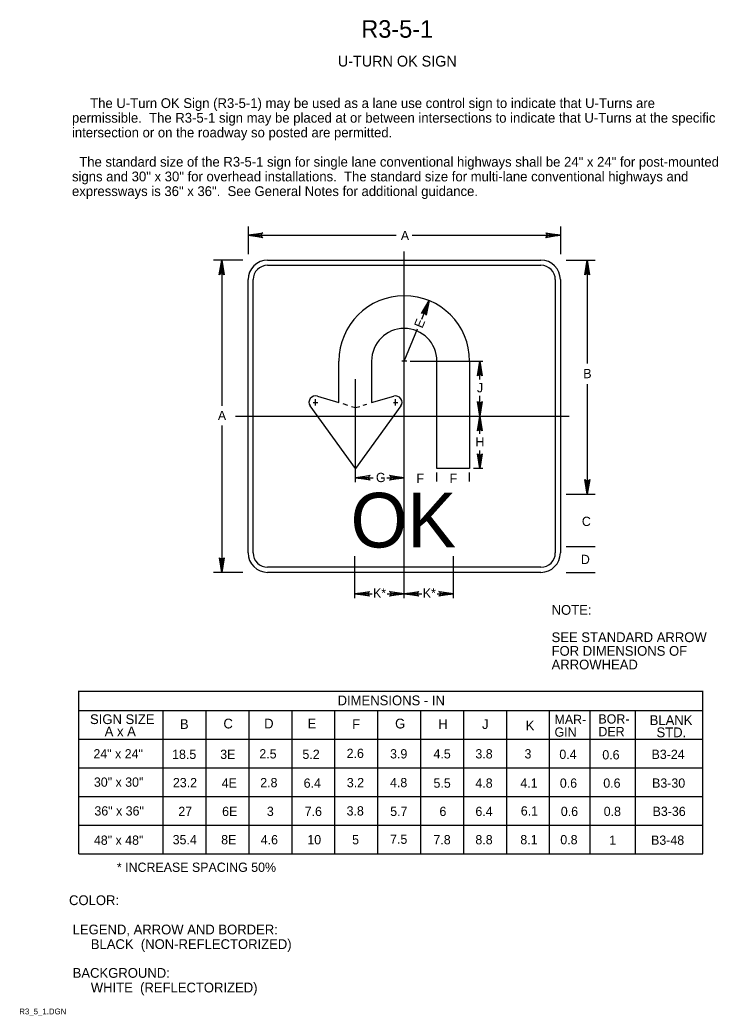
# Model space of a CAD drawing. Extents: x 0.013 to 0.191, y 0.004 to 0.259.
import ezdxf

# ---------------------------------------------------------------- set-up
doc = ezdxf.new("R2010")
doc.units = 0
for name, color, linetype in [('1', 7, 'Continuous'), ('11', 7, 'Continuous'), ('12', 7, 'Continuous'), ('3', 7, 'Continuous')]:
    doc.layers.add(name, color=color, linetype=linetype)

# ---------------------------------------------------------------- blocks, each defined once
blk = doc.blocks.new('RARROW')
at = {"layer": '3'}
for p, q in [((-2.156, 0.28500000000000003), (-2.2665, 0.384625)), ((-2.2665, 0.384625), (0, 0)), ((0, 0), (-2.2665, -0.379125)), ((-2.156, 0.28500000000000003), (-2.075625, 0.12075)), ((0, 0), (-2.156, 0.28500000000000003)), ((-2.14975, -0.2705), (0, 0)), ((-2.075625, 0.12075), (0, 0)), ((0, 0), (-2.074, -0.108)), ((-2.2665, -0.379125), (-2.14975, -0.2705)), ((-2.074, -0.108), (-2.14975, -0.2705))]:
    blk.add_line(p, q, dxfattribs=at)

msp = doc.modelspace()

# ---------------------------------------------------------------- linework, layer by layer
at = {"layer": '1'}
for p, q in [((0.07100000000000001, 0.20626642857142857), (0.07100000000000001, 0.19914142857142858)), ((0.151, 0.20626642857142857), (0.151, 0.19914142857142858)), ((0.07100000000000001, 0.20401642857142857), (0.10893749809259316, 0.20401642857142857)), ((0.11306250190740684, 0.20401642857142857), (0.151, 0.20401642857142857)), ((0.111, 0.11101642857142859), (0.111, 0.19989142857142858)), ((0.069625, 0.19764142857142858), (0.062125, 0.19764142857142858)), ((0.06425, 0.19764142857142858), (0.06425, 0.1602664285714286)), ((0.1525, 0.19764142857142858), (0.15987500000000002, 0.19764142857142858)), ((0.15787500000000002, 0.19764142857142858), (0.15787500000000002, 0.17114142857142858)), ((0.1155, 0.18251642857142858), (0.11737500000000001, 0.18726642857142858)), ((0.111, 0.17176688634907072), (0.11439386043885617, 0.18000911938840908)), ((0.111625, 0.17176642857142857), (0.110375, 0.17176642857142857)), ((0.1125, 0.17176642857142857), (0.131125, 0.17176642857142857)), ((0.130375, 0.1670164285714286), (0.130375, 0.17176642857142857)), ((0.0985, 0.14076642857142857), (0.0985, 0.16714142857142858)), ((0.15787500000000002, 0.16589142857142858), (0.15787500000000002, 0.13764142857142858)), ((0.08762500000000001, 0.16114142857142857), (0.088875, 0.16114142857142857)), ((0.08825, 0.16039142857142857), (0.08825, 0.1620164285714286)), ((0.09525, 0.16089142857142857), (0.0965, 0.1605164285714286)), ((0.10825, 0.16114142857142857), (0.109375, 0.16114142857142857)), ((0.10875, 0.16039142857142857), (0.10875, 0.1620164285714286)), ((0.130375, 0.15764142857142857), (0.130375, 0.16289142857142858)), ((0.0975, 0.16014142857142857), (0.0985, 0.15989142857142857)), ((0.0985, 0.15989142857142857), (0.099625, 0.16014142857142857)), ((0.1005, 0.1605164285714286), (0.101375, 0.1607664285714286)), ((0.06775, 0.15764142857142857), (0.15325, 0.15764142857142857)), ((0.130375, 0.15314142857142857), (0.130375, 0.15764142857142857)), ((0.06425, 0.15526642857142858), (0.06425, 0.11764142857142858)), ((0.130375, 0.14426642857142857), (0.130375, 0.1488914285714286)), ((0.098375, 0.1443914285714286), (0.0985, 0.14426642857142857)), ((0.11937500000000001, 0.14089142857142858), (0.11937500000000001, 0.14326642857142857)), ((0.12775, 0.14089142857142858), (0.12775, 0.14326642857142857)), ((0.131125, 0.14426642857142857), (0.12875, 0.14426642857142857)), ((0.0985, 0.1418918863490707), (0.10300000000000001, 0.1418918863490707)), ((0.1065, 0.14189142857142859), (0.111, 0.14189142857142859)), ((0.1525, 0.13764142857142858), (0.15987500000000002, 0.13764142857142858)), ((0.1525, 0.12426642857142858), (0.15987500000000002, 0.12426642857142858)), ((0.098375, 0.11101642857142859), (0.098375, 0.12176642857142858)), ((0.123625, 0.11101642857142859), (0.123625, 0.12176642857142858)), ((0.069625, 0.11764142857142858), (0.062125, 0.11764142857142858)), ((0.1525, 0.11764142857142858), (0.15987500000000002, 0.11764142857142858)), ((0.098375, 0.11214188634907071), (0.10275000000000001, 0.11214188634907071)), ((0.10664094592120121, 0.11214188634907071), (0.111, 0.11214188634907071)), ((0.111, 0.11214188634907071), (0.1155, 0.11214188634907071)), ((0.11945450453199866, 0.11214188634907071), (0.123625, 0.11214188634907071)), ((0.027625, 0.04551642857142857), (0.027625, 0.08726642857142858)), ((0.027631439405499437, 0.0872120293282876), (0.18750658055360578, 0.0872120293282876)), ((0.18750658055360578, 0.04550602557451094), (0.18750658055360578, 0.08725602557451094)), ((0.027618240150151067, 0.08223667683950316), (0.18750658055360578, 0.08223667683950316)), ((0.049255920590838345, 0.04548667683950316), (0.049255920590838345, 0.08225602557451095)), ((0.06025592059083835, 0.04548667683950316), (0.06025592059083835, 0.08225602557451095)), ((0.07125592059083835, 0.04548667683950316), (0.07125592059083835, 0.08225602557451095)), ((0.08225592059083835, 0.04548667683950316), (0.08225592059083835, 0.08225602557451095)), ((0.09325592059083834, 0.04548667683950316), (0.09325592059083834, 0.08225602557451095)), ((0.10425592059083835, 0.04548667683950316), (0.10425592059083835, 0.08225602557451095)), ((0.11525592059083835, 0.04548667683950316), (0.11525592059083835, 0.08225602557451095)), ((0.12625592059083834, 0.04548667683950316), (0.12625592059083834, 0.08225602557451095)), ((0.13725592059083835, 0.04548667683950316), (0.13725592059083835, 0.08225602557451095)), ((0.14825592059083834, 0.04548667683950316), (0.14825592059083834, 0.08225602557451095)), ((0.14825592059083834, 0.08225602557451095), (0.18750658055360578, 0.08225602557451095)), ((0.15864878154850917, 0.04550602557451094), (0.15864878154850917, 0.08225602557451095)), ((0.17021348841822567, 0.04550602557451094), (0.17021348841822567, 0.08225602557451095)), ((0.17025592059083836, 0.04548667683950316), (0.17025592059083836, 0.08225602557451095)), ((0.027618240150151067, 0.07488667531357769), (0.18750658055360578, 0.07488667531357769)), ((0.14825592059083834, 0.07490602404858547), (0.18750658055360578, 0.07490602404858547)), ((0.027618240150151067, 0.06753667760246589), (0.18750658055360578, 0.06753667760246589)), ((0.14825592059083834, 0.06755602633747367), (0.18750658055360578, 0.06755602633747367)), ((0.027618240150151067, 0.060186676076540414), (0.18750658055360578, 0.060186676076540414)), ((0.14825592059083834, 0.0602060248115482), (0.18750658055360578, 0.0602060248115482)), ((0.027618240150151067, 0.05283667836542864), (0.18750658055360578, 0.05283667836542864)), ((0.14825592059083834, 0.052856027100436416), (0.18750658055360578, 0.052856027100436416)), ((0.027618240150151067, 0.04548667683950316), (0.18750658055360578, 0.04548667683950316)), ((0.14825592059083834, 0.04550602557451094), (0.18750658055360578, 0.04550602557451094))]:
    msp.add_line(p, q, dxfattribs=at)
at = {"layer": '11'}
for p, q in [((0.076, 0.19764188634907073), (0.146, 0.19764188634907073)), ((0.07100000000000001, 0.12264188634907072), (0.07100000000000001, 0.19264188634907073)), ((0.151, 0.19264188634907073), (0.151, 0.12264188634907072)), ((0.146, 0.11764188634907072), (0.076, 0.11764188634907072))]:
    msp.add_line(p, q, dxfattribs=at)
for centre, start, end in [((0.076, 0.19264188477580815), 90, 180), ((0.146, 0.19264188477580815), 0, 90), ((0.076, 0.12264188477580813), 180, 270), ((0.146, 0.12264188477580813), 270, 0)]:
    msp.add_arc(centre, 0.005, start, end, dxfattribs=at)
at = {"layer": '12'}
for p, q in [((0.09425, 0.16114142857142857), (0.09425, 0.17176642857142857)), ((0.10262500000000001, 0.17176642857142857), (0.10262500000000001, 0.16114142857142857)), ((0.11937500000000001, 0.14426642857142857), (0.11937500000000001, 0.17176642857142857)), ((0.12775, 0.17176642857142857), (0.12775, 0.14426642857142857)), ((0.08875, 0.1627664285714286), (0.09425, 0.16114142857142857)), ((0.10262500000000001, 0.16114142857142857), (0.108375, 0.1627664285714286)), ((0.0985, 0.14426642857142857), (0.08687500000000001, 0.1602664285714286)), ((0.110125, 0.1602664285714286), (0.0985, 0.14426642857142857)), ((0.110125, 0.1602664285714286), (0.110125, 0.1602664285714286)), ((0.12775, 0.14426642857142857), (0.11937500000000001, 0.14426642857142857))]:
    msp.add_line(p, q, dxfattribs=at)
for centre, radius, start, end in [((0.11100000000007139, 0.17176688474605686), 0.01674999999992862, 0, 180), ((0.11100000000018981, 0.17176688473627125), 0.0083749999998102, 0, 180), ((0.08825336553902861, 0.1611895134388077), 0.0016586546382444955, 71.14958333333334, 213.7969388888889), ((0.10882617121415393, 0.16122020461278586), 0.0016111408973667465, 323.72191944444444, 106.26212222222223)]:
    msp.add_arc(centre, radius, start, end, dxfattribs=at)
at = {"layer": '3'}
for p, q in [((0.076, 0.196341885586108), (0.146, 0.196341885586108)), ((0.07230000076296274, 0.12264188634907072), (0.07230000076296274, 0.19264188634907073)), ((0.14969999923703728, 0.19264188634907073), (0.14969999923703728, 0.12264188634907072)), ((0.146, 0.11894188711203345), (0.076, 0.11894188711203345))]:
    msp.add_line(p, q, dxfattribs=at)
for centre, start, end in [((0.076, 0.19264188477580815), 90, 180), ((0.146, 0.19264188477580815), 0, 90), ((0.076, 0.12264188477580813), 180, 270), ((0.146, 0.12264188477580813), 270, 0)]:
    msp.add_arc(centre, 0.0037, start, end, dxfattribs=at)

# ---------------------------------------------------------------- block references
for p, xscale, yscale, rotation in [((0.07100000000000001, 0.20401642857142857), 0.0016545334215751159, 0.0016366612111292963, 180), ((0.06425, 0.19764142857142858), 0.0016545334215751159, 0.0016366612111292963, 90), ((0.15787500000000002, 0.19764142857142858), 0.0016545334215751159, 0.0016366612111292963, 90), ((0.11737500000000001, 0.18726642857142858), 0.001654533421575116, 0.001636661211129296, 68.65285198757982), ((0.130375, 0.17176642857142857), 0.0016545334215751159, 0.0016366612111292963, 90), ((0.130375, 0.15764142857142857), 0.0016545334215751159, 0.0016366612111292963, -90), ((0.130375, 0.15764142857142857), 0.0016545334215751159, 0.0016366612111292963, 90), ((0.130375, 0.14426642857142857), 0.0016545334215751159, 0.0016366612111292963, -90), ((0.0985, 0.14189142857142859), 0.0016545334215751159, 0.0016366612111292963, 180), ((0.15787500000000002, 0.13764142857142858), 0.0016545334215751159, 0.0016366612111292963, -90), ((0.06425, 0.11764142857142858), 0.0016545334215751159, 0.0016366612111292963, -90), ((0.098375, 0.11214142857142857), 0.0016545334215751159, 0.0016366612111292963, 180), ((0.111, 0.11214142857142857), 0.0016545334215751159, 0.0016366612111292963, 180)]:
    msp.add_blockref('RARROW', p, dxfattribs=dict(at, xscale=xscale, yscale=yscale, rotation=rotation))
at = {"layer": '3', "xscale": 0.0016545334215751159, "yscale": 0.0016366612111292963}
for p in [(0.151, 0.20401642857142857), (0.111, 0.14189142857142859), (0.111, 0.11214142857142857), (0.123625, 0.11214142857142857)]:
    msp.add_blockref('RARROW', p, dxfattribs=at)

# ---------------------------------------------------------------- texts
at = {"layer": '1'}
for s, height, p in [('R3-5-1', 0.0045000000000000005, (0.1, 0.254625)), ('U-TURN OK SIGN', 0.00275025, (0.094, 0.24725)), ('     The U-Turn OK Sign (R3-5-1) may be used as a lane use control sign to indicate that U-Turns are', 0.00250875, (0.025875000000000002, 0.23661625)), ('permissible.  The R3-5-1 sign may be placed at or between intersections to indicate that U-Turns at the specific', 0.00250875, (0.025875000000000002, 0.2328575)), ('intersection or on the roadway so posted are permitted.', 0.00250875, (0.025875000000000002, 0.22909875)), ('  The standard size of the R3-5-1 sign for single lane conventional highways shall be 24" x 24" for post-mounted ', 0.00250875, (0.025875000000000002, 0.22158125)), ('signs and 30" x 30" for overhead installations.  The standard size for multi-lane conventional highways and ', 0.00250875, (0.025875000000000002, 0.2178225)), ('expressways is 36" x 36".  See General Notes for additional guidance.', 0.00250875, (0.025875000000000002, 0.21406375)), ('A', 0.0023752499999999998, (0.110125, 0.20276642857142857)), ('B', 0.0023752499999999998, (0.15687500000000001, 0.16739142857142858)), ('J', 0.0023752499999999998, (0.129625, 0.1637664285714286)), ('A', 0.0023752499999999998, (0.06325, 0.15664142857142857)), ('H', 0.0023752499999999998, (0.12925, 0.1498914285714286)), ('G', 0.0023752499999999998, (0.10375000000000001, 0.14076642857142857)), ('F', 0.0023752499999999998, (0.114125, 0.14051642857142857)), ('F', 0.0023752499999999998, (0.122625, 0.14051642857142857)), ('C', 0.0023752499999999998, (0.1565, 0.1295164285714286)), ('D', 0.0023752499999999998, (0.15625, 0.11976642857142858)), ('K*', 0.0023752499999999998, (0.10300000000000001, 0.11114142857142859)), ('K*', 0.0023752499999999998, (0.11575, 0.11114142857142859)), ('NOTE:', 0.0024997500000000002, (0.14875, 0.10676642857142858)), ('SEE STANDARD ARROW', 0.0024997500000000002, (0.14875, 0.09976642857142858)), ('FOR DIMENSIONS OF', 0.0024997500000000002, (0.14875, 0.09626642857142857)), ('ARROWHEAD', 0.0024997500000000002, (0.14875, 0.09276642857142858)), ('DIMENSIONS - IN', 0.0024997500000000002, (0.09393211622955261, 0.08357815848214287)), ('SIGN SIZE', 0.0024997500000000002, (0.0305, 0.07876642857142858)), ('B', 0.0024997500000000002, (0.053528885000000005, 0.07751642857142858)), ('C', 0.0024997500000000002, (0.06467812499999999, 0.07764142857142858)), ('D', 0.0024997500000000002, (0.07510654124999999, 0.07764142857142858)), ('E', 0.0024997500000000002, (0.08624024, 0.07764142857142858)), ('F', 0.0024997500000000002, (0.09764743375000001, 0.07751642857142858)), ('G', 0.0024997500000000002, (0.10865729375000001, 0.07764142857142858)), ('H', 0.0024997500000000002, (0.1197387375, 0.07751642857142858)), ('J', 0.0024997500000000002, (0.13093642, 0.07751642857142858)), ('K', 0.0024997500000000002, (0.142125, 0.07714142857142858)), ('MAR-', 0.0023752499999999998, (0.1495, 0.07876642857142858)), ('BOR-', 0.0023752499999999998, (0.16075, 0.07889142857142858)), ('BLANK', 0.0024997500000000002, (0.173875, 0.07851642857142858)), ('A x A', 0.0024997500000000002, (0.03425, 0.07564142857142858)), ('GIN', 0.0023752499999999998, (0.1495, 0.07551642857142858)), ('DER', 0.0023752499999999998, (0.16075, 0.07564142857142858)), ('STD.', 0.0024997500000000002, (0.175625, 0.07539142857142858)), ('24" x 24"', 0.0023752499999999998, (0.03137041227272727, 0.06995380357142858)), ('B3-24', 0.0023752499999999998, (0.17436490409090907, 0.06982880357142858)), ('30" x 30"', 0.0023752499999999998, (0.03149541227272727, 0.06270380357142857)), ('B3-30', 0.0023752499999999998, (0.17449638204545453, 0.06245380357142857)), ('36" x 36"', 0.0023752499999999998, (0.03162041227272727, 0.055328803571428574)), ('B3-36', 0.0023752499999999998, (0.17462642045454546, 0.055203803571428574)), ('48" x 48"', 0.0023752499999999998, (0.03149541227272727, 0.047828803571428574)), ('B3-48', 0.0023752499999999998, (0.17423846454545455, 0.047828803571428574)), ('* INCREASE SPACING 50%', 0.0023752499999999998, (0.037375, 0.04089142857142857)), ('COLOR:', 0.0024997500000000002, (0.025125, 0.032375)), (' LEGEND, ARROW AND BORDER:', 0.0024997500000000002, (0.025125, 0.024875)), ('      BLACK  (NON-REFLECTORIZED)', 0.0024997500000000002, (0.025125, 0.021125)), (' BACKGROUND:', 0.0024997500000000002, (0.025125, 0.01375)), ('      WHITE  (REFLECTORIZED)', 0.0024997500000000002, (0.025125, 0.01)), ('R3_5_1.DGN', 0.0015, (0.012375, 0.004375))]:
    msp.add_text(s, height=height, dxfattribs=at).set_placement(p)
msp.add_text('E', height=0.0023752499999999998, rotation=67.65006111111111, dxfattribs=at).set_placement((0.115625, 0.18001642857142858))
at = {"layer": '12'}
msp.add_text('OK', height=0.01400025, dxfattribs=at).set_placement((0.09725, 0.12401642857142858))
at = {"layer": '3'}
for s, p in [('18.5', (0.05152661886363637, 0.06982880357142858)), ('3E', (0.06384860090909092, 0.06982880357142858)), ('2.5', (0.0738713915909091, 0.06995380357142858)), ('5.2', (0.08491997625, 0.06982880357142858)), ('2.6', (0.0962435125, 0.07007880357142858)), ('3.9', (0.10737211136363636, 0.06995380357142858)), ('4.5', (0.1184963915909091, 0.06995380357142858)), ('3.8', (0.1292305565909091, 0.06995380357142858)), ('3', (0.1418066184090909, 0.06995380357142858)), ('0.4', (0.15073199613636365, 0.06982880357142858)), ('0.6', (0.16174351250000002, 0.06970380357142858)), ('23.2', (0.051734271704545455, 0.06257880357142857)), ('4E', (0.0642236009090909, 0.06245380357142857)), ('2.8', (0.07410555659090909, 0.06257880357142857)), ('6.4', (0.08523199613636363, 0.06245380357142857)), ('3.2', (0.09629497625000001, 0.06257880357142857)), ('4.8', (0.10735555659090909, 0.06257880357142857)), ('5.5', (0.1184963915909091, 0.06245380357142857)), ('4.8', (0.1292305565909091, 0.06245380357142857)), ('4.1', (0.14074039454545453, 0.06245380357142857)), ('0.6', (0.15086851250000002, 0.06245380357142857)), ('0.6', (0.16199351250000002, 0.06245380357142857)), ('27', (0.05312199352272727, 0.055203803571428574)), ('6E', (0.0643486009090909, 0.055203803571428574)), ('3', (0.07580661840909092, 0.055203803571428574)), ('7.6', (0.0854935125, 0.055203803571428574)), ('3.8', (0.0962305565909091, 0.055328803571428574)), ('5.7', (0.10740414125, 0.055203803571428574)), ('6', (0.12002206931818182, 0.055203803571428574)), ('6.4', (0.12923199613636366, 0.055203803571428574)), ('6.1', (0.14086539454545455, 0.055328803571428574)), ('0.6', (0.15111851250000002, 0.055203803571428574)), ('0.8', (0.16210555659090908, 0.055203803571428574)), ('35.4', (0.051671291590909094, 0.047953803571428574)), ('8E', (0.0640986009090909, 0.047953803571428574)), ('4.6', (0.0742435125, 0.047953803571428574)), ('10', (0.08617225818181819, 0.047953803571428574)), ('5', (0.09764994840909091, 0.047953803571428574)), ('7.5', (0.1073713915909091, 0.048078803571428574)), ('7.8', (0.11848055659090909, 0.047953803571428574)), ('8.8', (0.1292305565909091, 0.047953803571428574)), ('8.1', (0.14074039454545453, 0.047953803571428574)), ('0.8', (0.1509805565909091, 0.047953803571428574)), ('1', (0.16351895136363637, 0.047828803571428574))]:
    msp.add_text(s, height=0.0023752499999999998, dxfattribs=at).set_placement(p)

doc.saveas('drawing.dxf')
